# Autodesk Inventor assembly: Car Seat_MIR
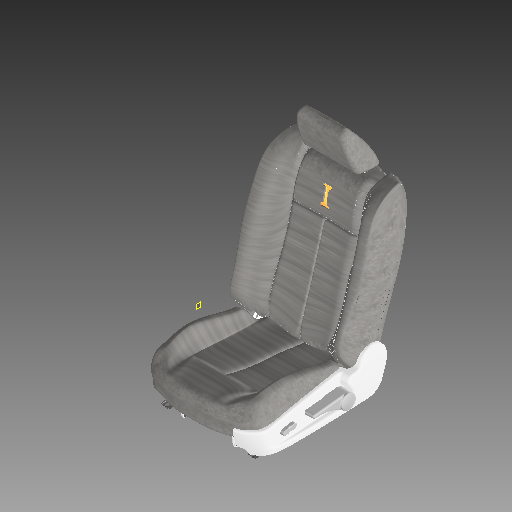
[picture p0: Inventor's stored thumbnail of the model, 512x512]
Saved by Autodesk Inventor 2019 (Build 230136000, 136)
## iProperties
Company: Autodesk Inc.
Created: 2007-12
Part Number: Car Seat_MIR
Description: SUPER CAR DRIVER SEAT 1000
Document SubType Name: Assembly
Designer: Autodesk Inc.
Mass: 63194.5 g
Surface Area: 75615.4 cm^2
Volume: 49572.3 cm^3
Density: 1.27479 g/cm^3
Author: Inventor
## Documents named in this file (20)
- C:\TEMP\Car Seat\Workspace\Car Seat_MIR.iam
- C:\TEMP\Car Seat\Workspace\Lower Full Assembly_MIR.iam
- C:\TEMP\Car Seat\Workspace\Back Frame Main Assembly.iam
- C:\TEMP\Car Seat\Workspace\Headrest.iam
- C:\TEMP\Car Seat\Workspace\Spring Holder Pin_MIR.ipt
- C:\TEMP\Car Seat\Workspace\Side Handle Pivot Pin_MIR.ipt
- C:\TEMP\Car Seat\Workspace\Bell Crank Side Handle_MIR.ipt
- C:\TEMP\Car Seat\Workspace\Rear Pivot Lock Plate_MIR.ipt
- C:\TEMP\Car Seat\Workspace\Rear Tilt Spring_MIR.ipt
- C:\TEMP\Car Seat\Workspace\Wire Holder A_MIR.ipt
- C:\TEMP\Car Seat\Workspace\Wire Holder B_MIR.ipt
- C:\TEMP\Car Seat\Workspace\Side Link Bar_MIR.ipt
- C:\TEMP\Car Seat\Workspace\Side Cover_MIR.ipt
- C:\TEMP\Car Seat\Workspace\Handle_MIR.ipt
- C:\TEMP\Car Seat\Workspace\Power Switch Control_MIR.ipt
- C:\TEMP\Car Seat\Workspace\Upper Seat Cover.ipt
- C:\TEMP\Car Seat\Workspace\Lower Seat Cushion_MIR.ipt
- C:\TEMP\Car Seat\Workspace\Upper Seat Cushion.ipt
- C:\TEMP\Car Seat\Workspace\Power Switch Tab.ipt
- C:\TEMP\Car Seat\Workspace\Control Switch Connector.ipt
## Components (19 placed, 19 different names)
1. Lower Full Assembly_MIR:1 [sub-assembly] — Angle:4, Mate:25, Flush:1, Insert:1, Flush:6, Flush:5, Flush:4, Insert:6, Mate:27
2. Back Frame Main Assembly:1 [sub-assembly] — Angle:4, Mate:25, Flush:1, Angle:1, Mate:11, Mate:19, Mate:18, Flush:2, Mate:26
3. Headrest:1 [sub-assembly] — Mate:19, Mate:18, Flush:2
4. Spring Holder Pin_MIR:1 — Insert:1, Tangent:3, Tangent:2
5. Side Handle Pivot Pin_MIR:1 — Mate:5, Mate:4, Mate:27, Mate:26, Insert:6
6. Bell Crank Side Handle_MIR:1 — Mate:5, Mate:4, Angle:5, Insert:7
7. Rear Pivot Lock Plate_MIR:1 — Angle:1, Mate:26, Mate:27, Mate:28
8. Rear Tilt Spring_MIR:1 — Tangent:3, Tangent:2, Mate:11
9. Wire Holder A_MIR:1 — Mate:15, Mate:14, Insert:7
10. Wire Holder B_MIR:1 — Mate:13, Mate:12
11. Side Link Bar_MIR:1 — Mate:15, Mate:14, Mate:13, Mate:12, Mate:28
12. Side Cover_MIR:1 — Flush:6, Flush:5, Flush:4, Mate:30, Mate:29, Mate:28
13. Handle_MIR:1 — Angle:5, Mate:27, Mate:26
14. Power Switch Control_MIR:1 — Mate:30, Mate:29, Mate:28, Mate:31, Insert:6_1, Mate:34, Mate:33, Mate:32
15. Power Switch Tab:1 — Mate:31, Insert:6_1
16. Control Switch Connector:1 — Mate:34, Mate:33, Mate:32
17. Upper Seat Cover:1 — Flush:7, Flush:11, Flush:10, Flush:9
18. Lower Seat Cushion_MIR:1 — Flush:8
19. Upper Seat Cushion:1 — Flush:11, Flush:10, Flush:9
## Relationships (41: Mate 26, Flush 6, Insert 4, Angle 3, Tangent 2)
- Angle:4: Lower Full Assembly_MIR:1 ↔ Back Frame Main Assembly:1
- Mate:25: Lower Full Assembly_MIR:1 ↔ Back Frame Main Assembly:1
- Flush:1 [Mate]: Lower Full Assembly_MIR:1 ↔ Back Frame Main Assembly:1
- Insert:1: Lower Full Assembly_MIR:1 ↔ Spring Holder Pin_MIR:1
- Mate:5: Side Handle Pivot Pin_MIR:1 ↔ Bell Crank Side Handle_MIR:1
- Mate:4: Side Handle Pivot Pin_MIR:1 ↔ Bell Crank Side Handle_MIR:1
- Angle:1: Back Frame Main Assembly:1 ↔ Rear Pivot Lock Plate_MIR:1
- Tangent:3: Spring Holder Pin_MIR:1 ↔ Rear Tilt Spring_MIR:1
- Tangent:2: Spring Holder Pin_MIR:1 ↔ Rear Tilt Spring_MIR:1
- Mate:11: Back Frame Main Assembly:1 ↔ Rear Tilt Spring_MIR:1
- Mate:15: Wire Holder A_MIR:1 ↔ Side Link Bar_MIR:1
- Mate:14: Wire Holder A_MIR:1 ↔ Side Link Bar_MIR:1
- Mate:13: Wire Holder B_MIR:1 ↔ Side Link Bar_MIR:1
- Mate:12: Wire Holder B_MIR:1 ↔ Side Link Bar_MIR:1
- Mate:19: Back Frame Main Assembly:1 ↔ Headrest:1
- Mate:18: Back Frame Main Assembly:1 ↔ Headrest:1
- Flush:2: Back Frame Main Assembly:1 ↔ Headrest:1
- Flush:6 [Mate]: Lower Full Assembly_MIR:1 ↔ Side Cover_MIR:1
- Flush:5: Lower Full Assembly_MIR:1 ↔ Side Cover_MIR:1
- Flush:4 [Mate]: Lower Full Assembly_MIR:1 ↔ Side Cover_MIR:1
- Angle:5: Bell Crank Side Handle_MIR:1 ↔ Handle_MIR:1
- Mate:27: Side Handle Pivot Pin_MIR:1 ↔ Handle_MIR:1
- Mate:26: Side Handle Pivot Pin_MIR:1 ↔ Handle_MIR:1
- Mate:30: Side Cover_MIR:1 ↔ Power Switch Control_MIR:1
- Mate:29: Side Cover_MIR:1 ↔ Power Switch Control_MIR:1
- Mate:28: Side Cover_MIR:1 ↔ Power Switch Control_MIR:1
- Mate:31: Power Switch Control_MIR:1 ↔ Power Switch Tab:1
- Insert:6_1: Power Switch Control_MIR:1 ↔ Power Switch Tab:1
- Mate:34: Power Switch Control_MIR:1 ↔ Control Switch Connector:1
- Mate:33: Power Switch Control_MIR:1 ↔ Control Switch Connector:1
- Mate:32: Power Switch Control_MIR:1 ↔ Control Switch Connector:1
- Flush:7 [Mate]: Upper Seat Cover:1
- Flush:8: Lower Seat Cushion_MIR:1
- Flush:11: Upper Seat Cover:1 ↔ Upper Seat Cushion:1
- Flush:10: Upper Seat Cover:1 ↔ Upper Seat Cushion:1
- Flush:9: Upper Seat Cover:1 ↔ Upper Seat Cushion:1
- Insert:6: Lower Full Assembly_MIR:1 ↔ Side Handle Pivot Pin_MIR:1
- Insert:7: Bell Crank Side Handle_MIR:1 ↔ Wire Holder A_MIR:1
- Mate:26: Back Frame Main Assembly:1 ↔ Rear Pivot Lock Plate_MIR:1
- Mate:27: Lower Full Assembly_MIR:1 ↔ Rear Pivot Lock Plate_MIR:1
- Mate:28: Rear Pivot Lock Plate_MIR:1 ↔ Side Link Bar_MIR:1
